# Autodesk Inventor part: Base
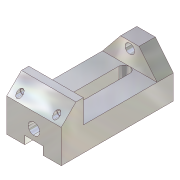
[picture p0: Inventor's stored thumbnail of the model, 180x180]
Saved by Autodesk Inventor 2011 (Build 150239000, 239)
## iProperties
Shininess: 77.0
Length Units: 11269
Angle Units: 11279
Time Units: 11290
Mass Units: 11283
Length Display Precision: 3
Angle Display Precision: 2
Created: 2002-02
Part Number: Base
Document SubType Name: Modeling
Designer: ***
Density: 1 g/cm^3
Density: 0.0
Volumn: 0.0
Area: 0.0
PropertySet Name: Model Information
Control State: 0
Master: False
Checked Out: False
Author: ***
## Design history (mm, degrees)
sketch "Sketch2"
  geometry: L1 (-63.961, -4.254)-(-63.961, -37.254); L2 (-63.961, -37.254)-(88.039, -37.254); L3 (88.039, -37.254)-(88.039, 7.746); L4 (88.039, 7.746)-(68.039, 27.746); L5 (68.039, 27.746)-(58.039, 27.746); L6 (58.039, 27.746)-(58.039, -4.254); L7 (58.039, -4.254)-(-63.961, -4.254)
  constraints: 14 end point, 4 parallel, 1 perpendicular, 1 vertical
  dimensions: "d7" = 10 distance of L4.end L5.end; "d8" = 135 deg angle of L3 L4; "d9" = 33 distance of L1.start L1.end; "d10" = 152 distance of L1.end L2.end; "d11" = 65 distance between parallel lines of L5 L2; "d21" = 30 distance between parallel lines of L3 L6
extrude "Extrusion1" new body sketch "Sketch2" stored distance "d13" = 74; taper "d14" = 0 deg
sketch "Sketch3"
  geometry: L1 (0, 74)-(0, 0) reference; L2 (0, 0)-(-30, 24.5); L3 (-30, 24.5)-(-30, 49.5); L4 (-30, 49.5)-(0, 74); C1 r 6.5 at (-21, 37)
  constraints: 6 end point, 1 centre point, 1 equal length, 1 parallel
  dimensions: "d15" = 25 distance of L2.end L3.end; "d16" = 30 distance between parallel lines of L3 L1; "d17" = 13 diameter of C1; "d18" = 9 distance from line of L3 C1.centre
extrude "Extrusion2" join sketch "Sketch3" distance "d19" = 22; taper "d20" = 0 deg
sketch "Sketch4"
  geometry: L1 (0, 0)-(0, 74) reference; L2 (0, 0)-(45, 0) reference; C1 r 8 at (25, 37)
  constraints: 1 centre point
  dimensions: "d22" = 16 diameter of C1; "d23" = 25 distance from line of L1 C1.centre; "d24" = 37 distance from line of L2 C1.centre
extrude "Extrusion3" cut sketch "Sketch4" distance "d25" = 13; taper "d26" = 0 deg
sketch "Sketch5"
  geometry: L1 (45, 74)-(0, 74) reference; L2 (65, 0)-(65, 74) reference; 1 further point
  dimensions: "d27" = 12 distance from line of point (51, 62) L1; "d28" = 14 distance from line of L2 point (51, 62)
hole "Hole1" sketch "Sketch5" at (51, 62) diameter "d29" = 6; stored, may be unused: countersink angle "d33" = 82 deg, drill point angle "d35" = 0 deg; dims "d30" = 6, "d31" = 8, "d32" = 10, "d34" = 30
mirror "Mirror1"
sketch "Sketch6"
  geometry: L1 (100, 0)-(100, 74) reference; L2 (100, 74)-(0, 74) reference; L3 (14, 45)-(92, 45); L4 (92, 29)-(14, 29); A1 r 8 centre (92, 37) between (92, 29) and (92, 45); A2 r 8 centre (14, 37) between (14, 45) and (14, 29)
  constraints: 4 end point, 4 point on circle, 4 tangent, 2 centre point, 1 horizontal, 1 parallel
  dimensions: "d36" = 8 radius of A2; "d37" = 78 distance of L4.start L4.end; "d38" = 8 distance from line of L1 A1.centre; "d39" = 37 distance from line of L2 A2.centre
extrude "Extrusion4" cut sketch "Sketch6" stored distance "d40" = 13; taper "d41" = 0 deg
sketch "Sketch7"
  geometry: L1 (0, 49.5)-(11, 49.5); L2 (11, 49.5)-(11, 24.5); L3 (11, 24.5)-(0, 24.5); L4 (0, 24.5)-(0, 49.5); L5 (45, 74)-(0, 74) reference; L6 (0, 0)-(0, 74) reference
  constraints: 8 end point, 2 parallel, 1 collinear, 1 horizontal, 1 perpendicular
  dimensions: "d42" = 25 distance of L3.end L1.start; "d43" = 11 distance of L1.start L1.end; "d44" = 24.5 distance between parallel lines of L5 L1
extrude "Extrusion5" cut sketch "Sketch7" stored distance "d45" = 13; taper "d46" = 0 deg
body "Solid1"
